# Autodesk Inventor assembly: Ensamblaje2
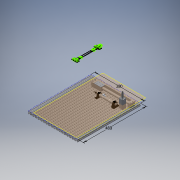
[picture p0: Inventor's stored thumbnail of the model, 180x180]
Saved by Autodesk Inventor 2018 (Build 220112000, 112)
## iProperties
Created: 2020-12
Part Number: Ensamblaje2
Material: Genérico
Document SubType Name: Assembly
Designer: ATOUZA
Author: ATOUZA
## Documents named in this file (5)
- D:\01 Paralaia\Grupos de Traballo\GT Maquetas\CAD 3D\E_Alimentación\Ensamblaje2.iam
- D:\01 Paralaia\Grupos de Traballo\GT Maquetas\CAD 3D\E_Alimentación\Perfil 20x20 B R6 480.ipt
- D:\01 Paralaia\Grupos de Traballo\GT Maquetas\CAD 3D\E_Alimentación\CY3R\SMC_JP_CY3R15200M9B000\CY3R15-200-M9B(0_0_0).iam
- D:\01 Paralaia\Grupos de Traballo\GT Maquetas\CAD 3D\E_Alimentación\CD85N\SMC_JP_CD85N1650MBM9B000\CD85N16-50M-B-M9B(0__0_0).iam
- D:\01 Paralaia\Grupos de Traballo\GT Maquetas\CAD 3D\E_Alimentación\MKB\SMC_JP_MKB1630LZM9B00\MKB16-30LZ-M9B(0_0).iam
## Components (22 placed, 4 different names)
1. CY3R15-200-M9B(0_0_0):1 [sub-assembly] — Coincidencia:1, Coincidencia:4
2. CD85N16-50M-B-M9B(0__0_0):1 [sub-assembly] — Coincidencia:2, Nivelación:1
3. MKB16-30LZ-M9B(0_0):1 [sub-assembly] — Coincidencia:3
4. Perfil 20x20 B R6 480:1 — Coincidencia:1, Coincidencia:2, Coincidencia:3, Ángulo:1
5. Perfil 20x20 B R6 480:2 — Nivelación:1
6. Perfil 20x20 B R6 480:3
7. Perfil 20x20 B R6 480:4
8. Perfil 20x20 B R6 480:5
9. Perfil 20x20 B R6 480:6
10. Perfil 20x20 B R6 480:7
11. Perfil 20x20 B R6 480:8
12. Perfil 20x20 B R6 480:9
13. Perfil 20x20 B R6 480:10
14. Perfil 20x20 B R6 480:11
15. Perfil 20x20 B R6 480:12
16. Perfil 20x20 B R6 480:13
17. Perfil 20x20 B R6 480:14
18. Perfil 20x20 B R6 480:15
19. Perfil 20x20 B R6 480:16
20. Perfil 20x20 B R6 480:17
21. Perfil 20x20 B R6 480:18
22. Perfil 20x20 B R6 480:19
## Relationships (6: Mate 4, Flush 1, Angle 1)
- Coincidencia:1 [Mate]: CY3R15-200-M9B(0_0_0):1 ↔ Perfil 20x20 B R6 480:1
- Coincidencia:2 [Mate]: CD85N16-50M-B-M9B(0__0_0):1 ↔ Perfil 20x20 B R6 480:1
- Nivelación:1 [Flush]: CD85N16-50M-B-M9B(0__0_0):1 ↔ Perfil 20x20 B R6 480:2
- Coincidencia:3 [Mate]: MKB16-30LZ-M9B(0_0):1 ↔ Perfil 20x20 B R6 480:1
- Coincidencia:4 [Mate]: CY3R15-200-M9B(0_0_0):1
- Ángulo:1 [Angle]: Perfil 20x20 B R6 480:1
